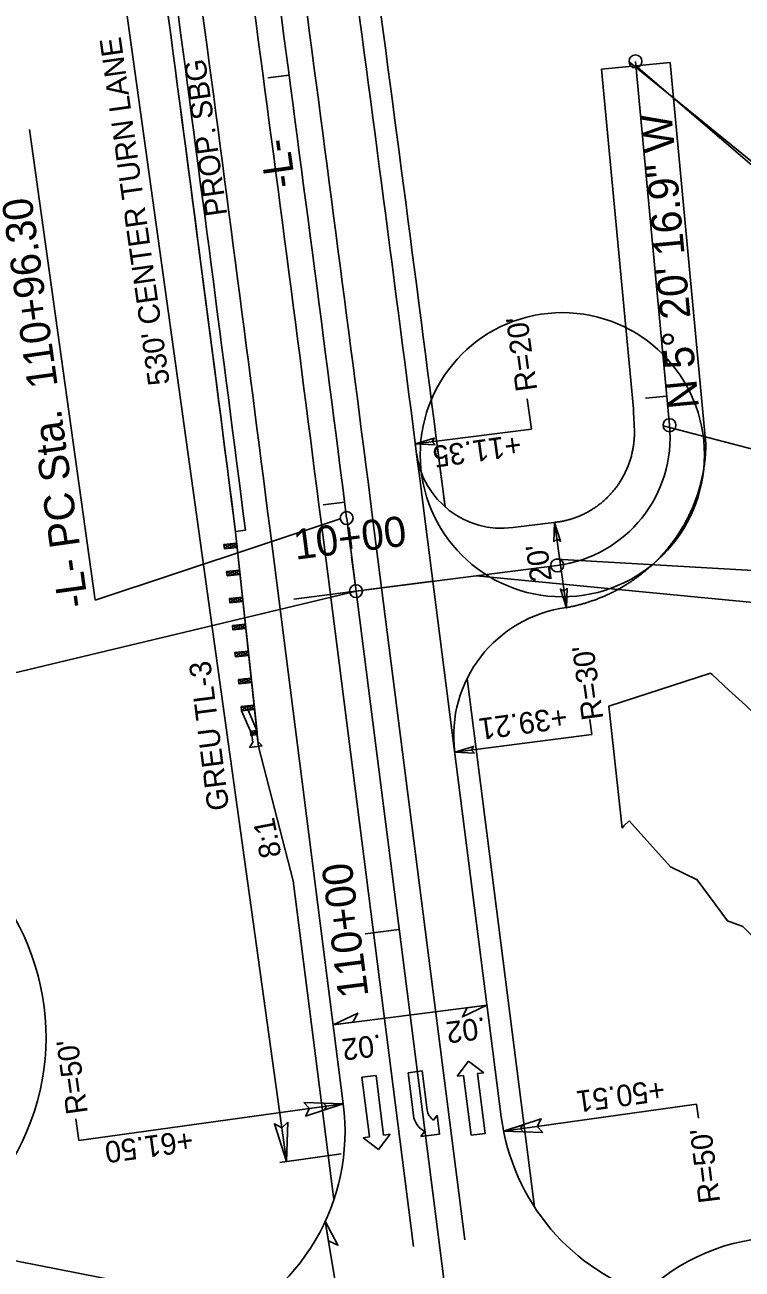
# Model space of a CAD drawing. Extents: x 472216 to 481979, y 489069 to 507339.
# Drawn here: x 477985.7 to 478152.3, y 497530.3 to 497819.2 of the extents above; entities that cross this region are included whole.
import ezdxf

# ---------------------------------------------------------------- set-up
doc = ezdxf.new("R2010")
doc.units = 0
for name, color, linetype in [('Old_Level_12', 7, 'Continuous'), ('Prop Drainage Structure Drop Inlet Grate 2 Narrow Slots and Sag Grates 840 24 CELL', 7, 'Continuous'), ('Prop Drainage Structure Drop Inlet Grate 2 Wide Slots and Sag Grates 840 22 Label', 7, 'Continuous'), ('Prop Drainage Structure Outlet Berm Ditch 850 10 CELL', 7, 'Continuous'), ('Prop Drainage Structure Pipe CSP 15in', 7, 'Continuous'), ('Prop Drainage Structure Pipe Plug CELL', 7, 'Continuous'), ('Prop Drainage Structure Pipe RCP 15in Class III Label', 7, 'Continuous'), ('Prop Drainage Structure Pipe RCP 24in Class III Label', 7, 'Continuous'), ('Prop Drainage Structure Pipe Side Drain 15in Label', 7, 'Continuous'), ('Prop Drainage Structure Tops and Inverts LABEL', 7, 'Continuous'), ('Prop Earthen Structure False Sump CELL', 7, 'Continuous'), ('Prop Earthen Structure Head Ditch', 7, 'Continuous'), ('Prop Erosion Embankment Toe Protection CELL', 7, 'Continuous'), ('Sheet Block Revision CELL', 7, 'Continuous'), ('Sheet North Arrow Point CELL', 7, 'Continuous'), ('Sheet PE Seal Cell', 7, 'Continuous'), ('Sheet Plan And Profile CELL', 7, 'Continuous'), ('Sheet Plot Border Outside CELL', 7, 'Continuous'), ('Sheet Profile Grid Major CELL', 7, 'Continuous'), ('Sheet Profile Grid Minor CELL', 7, 'Continuous')]:
    doc.layers.add(name, color=color, linetype=linetype)

msp = doc.modelspace()

# ---------------------------------------------------------------- linework, layer by layer
at = {"layer": 'Old_Level_12'}
for p, q in [((478126.01, 497810.56), (478297.2, 497671.33)), ((478127.6, 497809.67), (478261.36, 497694.97)), ((478002.05, 497685.61), (477986.84, 497794.87)), ((478133.9, 497726.09), (478246.46, 497696.58)), ((478058.97, 497704.48), (478002.05, 497685.61)), ((478109.14, 497695.17), (478233.08, 497687.85)), ((478218.13, 497678.87), (478090.63, 497691.29)), ((477920.08, 497653.64), (478062.62, 497687.71)), ((478085.17, 497512.33), (477786.24, 497570.88))]:
    msp.add_line(p, q, dxfattribs=at)
for centre in [(478127.51, 497810.7), (478135.4, 497726.23), (478060.46, 497704.67), (478060.46, 497704.67), (478109.33, 497693.68), (478062.62, 497687.71)]:
    msp.add_circle(centre, 1.5, dxfattribs=at)
at = {"layer": 'Prop Drainage Structure Drop Inlet Grate 2 Narrow Slots and Sag Grates 840 24 CELL'}
for points in [[(478093.03, 497591.58), (478087.33, 497588.85), (478088.45, 497591)], [(478057.33, 497587.03), (478063.03, 497589.76), (478061.92, 497587.61)], [(478055.48, 497541.43), (478058.43, 497535.84), (478056.24, 497536.86)]]:
    msp.add_lwpolyline(points, close=True, dxfattribs=at)
at = {"layer": 'Prop Drainage Structure Drop Inlet Grate 2 Wide Slots and Sag Grates 840 22 Label'}
for p, q in [((478057.33, 497587.03), (478093.04, 497591.58)), ((478055.48, 497541.43), (478069.85, 497454.82))]:
    msp.add_line(p, q, dxfattribs=at)
at = {"layer": 'Prop Drainage Structure Outlet Berm Ditch 850 10 CELL'}
for points in [[(478080.96, 497721.67), (478076.4, 497721.89), (478080.79, 497723.23), (478080.32, 497722.37)], [(478108.57, 497699.12), (478108.72, 497703.68), (478110.13, 497699.31), (478109.26, 497699.77)], [(478111.64, 497688.38), (478111.49, 497683.82), (478110.07, 497688.19), (478110.95, 497687.73)], [(478090.1, 497650.1), (478085.54, 497650.32), (478089.93, 497651.67), (478089.46, 497650.8)], [(478050.54, 497568.97), (478059.67, 497568.68), (478050.93, 497565.85), (478051.85, 497567.59)], [(478055.1, 497568.85), (478059.67, 497568.7), (478055.29, 497567.29), (478055.75, 497568.16)], [(478046.79, 497564.43), (478046.5, 497555.31), (478043.67, 497564.05), (478045.41, 497563.13)], [(478106.01, 497562.05), (478096.89, 497562.35), (478105.63, 497565.18), (478104.71, 497563.44)], [(478101.45, 497562.2), (478096.89, 497562.35), (478101.26, 497563.76), (478100.8, 497562.89)]]:
    msp.add_lwpolyline(points, close=True, dxfattribs=at)
at = {"layer": 'Prop Drainage Structure Pipe Plug CELL'}
for p, q in [((478034.67, 497701.38), (478039.66, 497654.89)), ((478034.94, 497698.85), (478031.95, 497698.53)), ((478033.55, 497697.69), (478031.95, 497698.53)), ((478031.95, 497698.53), (478032.06, 497697.53)), ((478032.06, 497697.53), (478033.45, 497698.69)), ((478035.04, 497697.85), (478032.06, 497697.53)), ((478033.45, 497698.69), (478033.55, 497697.69)), ((478033.45, 497698.69), (478035.04, 497697.85)), ((478033.55, 497697.69), (478034.94, 497698.85)), ((478035.04, 497697.85), (478033.55, 497697.69)), ((478034.94, 497698.85), (478035.04, 497697.85)), ((478035.61, 497692.58), (478032.57, 497692.26)), ((478034.2, 497691.42), (478032.57, 497692.26)), ((478032.57, 497692.26), (478032.68, 497691.26)), ((478032.68, 497691.26), (478034.09, 497692.42)), ((478035.72, 497691.59), (478032.68, 497691.26)), ((478034.09, 497692.42), (478034.2, 497691.42)), ((478034.09, 497692.42), (478035.72, 497691.59)), ((478035.61, 497692.58), (478034.2, 497691.42)), ((478036.28, 497686.32), (478033.25, 497685.99)), ((478034.87, 497685.16), (478033.25, 497685.99)), ((478033.25, 497685.99), (478033.36, 497685)), ((478033.36, 497685), (478034.77, 497686.15)), ((478034.77, 497686.15), (478034.87, 497685.16)), ((478034.77, 497686.15), (478036.39, 497685.32)), ((478036.28, 497686.32), (478034.87, 497685.16)), ((478036.39, 497685.32), (478033.36, 497685)), ((478036.96, 497680.05), (478033.94, 497679.73)), ((478034.04, 497678.73), (478035.45, 497679.89)), ((478035.45, 497679.89), (478035.55, 497678.89)), ((478035.45, 497679.89), (478037.06, 497679.06)), ((478036.96, 497680.05), (478035.55, 497678.89)), ((478036.96, 497680.05), (478037.06, 497679.06)), ((478035.55, 497678.89), (478033.94, 497679.73)), ((478033.94, 497679.73), (478034.04, 497678.73)), ((478037.06, 497679.06), (478034.04, 497678.73)), ((478037.63, 497673.79), (478034.51, 497673.45)), ((478036.18, 497672.63), (478034.51, 497673.45)), ((478034.51, 497673.45), (478034.62, 497672.46)), ((478034.62, 497672.46), (478036.07, 497673.62)), ((478037.73, 497672.79), (478034.62, 497672.46)), ((478036.07, 497673.62), (478036.18, 497672.63)), ((478036.07, 497673.62), (478037.73, 497672.79)), ((478037.63, 497673.79), (478036.18, 497672.63)), ((478038.3, 497667.52), (478035.32, 497667.2)), ((478036.92, 497666.37), (478035.32, 497667.2)), ((478035.32, 497667.2), (478035.43, 497666.21)), ((478035.43, 497666.21), (478036.81, 497667.36)), ((478038.41, 497666.53), (478035.43, 497666.21)), ((478036.81, 497667.36), (478036.92, 497666.37)), ((478036.81, 497667.36), (478038.41, 497666.53)), ((478038.3, 497667.52), (478036.92, 497666.37)), ((478038.97, 497661.26), (478035.93, 497660.93)), ((478037.56, 497660.1), (478035.93, 497660.93)), ((478035.93, 497660.93), (478036.03, 497659.93)), ((478036.03, 497659.93), (478037.45, 497661.09)), ((478039.08, 497660.26), (478036.03, 497659.93)), ((478036.03, 497659.93), (478038.11, 497655.23)), ((478037.45, 497661.09), (478037.56, 497660.1)), ((478037.45, 497661.09), (478039.08, 497660.26)), ((478038.97, 497661.26), (478037.56, 497660.1)), ((478037.56, 497660.1), (478039.6, 497655.39)), ((478039.6, 497655.39), (478038.11, 497655.23)), ((478038.11, 497655.23), (478038.17, 497654.73)), ((478039.71, 497654.39), (478038.11, 497655.23)), ((478038.11, 497655.23), (478038.22, 497654.23)), ((478038.22, 497654.23), (478039.6, 497655.39)), ((478039.71, 497654.39), (478038.22, 497654.23)), ((478038.37, 497654.7), (478038.98, 497654.78)), ((478038.63, 497652.67), (478038.37, 497654.7)), ((478038.98, 497654.78), (478039.59, 497654.85)), ((478039.59, 497654.85), (478039.84, 497652.82)), ((478037.93, 497651.39), (478038.63, 497652.67)), ((478040.84, 497651.76), (478037.93, 497651.39)), ((478039.84, 497652.82), (478040.84, 497651.76))]:
    msp.add_line(p, q, dxfattribs=at)
at = {"layer": 'Prop Drainage Structure Pipe RCP 15in Class III Label'}
for p, q in [((478075.99, 497535.59), (478054.5, 497703.91)), ((478087.89, 497537.11), (478066.41, 497705.43))]:
    msp.add_line(p, q, dxfattribs=at)
for radius in [22006, 21994]:
    msp.add_arc((456237.54, 494918.9), radius, 7.274664, 7.922681, dxfattribs=at)
at = {"layer": 'Prop Drainage Structure Pipe RCP 24in Class III Label'}
for p, q in [((478135.57, 497810.42), (478119.64, 497808.93)), ((478143.84, 497721.87), (478135.57, 497810.42)), ((478127.01, 497730.04), (478119.64, 497808.93)), ((478096.34, 497565.69), (478078.31, 497706.95)), ((478099.05, 497702.45), (478108.51, 497703.66)), ((478036.95, 497701.87), (478034.64, 497701.58)), ((478059.67, 497568.69), (478042.6, 497702.39))]:
    msp.add_line(p, q, dxfattribs=at)
for centre, radius, start, end in [((456237.54, 494918.9), 21982, 7.274664, 7.922681), ((456237.54, 494918.9), 22018, 7.274664, 7.90894), ((478096.51, 497722.29), 20, 187.3082, 277.2843), ((478115.3, 497654.12), 30, 97.2843, 187.2747), ((477934.66, 497584.21), 56, 329.137, 50.2504), ((478010.07, 497562.36), 50, 291.5633, 7.2747), ((478145.94, 497572.02), 50, 187.2747, 253.5242)]:
    msp.add_arc(centre, radius, start, end, dxfattribs=at)
for points in [[(478108.51, 497703.66), (478108.96, 497703.71), (478109.41, 497703.77), (478109.86, 497703.83), (478110.31, 497703.91), (478110.75, 497703.99), (478111.19, 497704.09), (478111.64, 497704.2), (478112.08, 497704.31), (478112.52, 497704.44), (478112.95, 497704.58), (478113.39, 497704.73), (478113.82, 497704.88), (478114.24, 497705.05), (478114.67, 497705.23), (478115.09, 497705.41), (478115.5, 497705.61), (478115.92, 497705.82), (478116.33, 497706.03), (478116.73, 497706.26), (478117.13, 497706.49), (478117.52, 497706.73), (478117.91, 497706.99), (478118.3, 497707.25), (478118.68, 497707.52), (478119.05, 497707.8), (478119.42, 497708.09), (478119.78, 497708.38), (478120.13, 497708.69), (478120.48, 497709), (478120.82, 497709.33), (478121.16, 497709.66), (478121.48, 497709.99), (478121.8, 497710.34), (478122.11, 497710.69), (478122.42, 497711.05), (478122.72, 497711.42), (478123, 497711.8), (478123.29, 497712.18), (478123.56, 497712.57), (478123.82, 497712.96), (478124.08, 497713.37), (478124.32, 497713.77), (478124.56, 497714.19), (478124.79, 497714.61), (478125.01, 497715.03), (478125.22, 497715.46), (478125.42, 497715.9), (478125.61, 497716.34), (478125.79, 497716.78), (478125.96, 497717.23), (478126.12, 497717.69), (478126.27, 497718.15), (478126.41, 497718.61), (478126.54, 497719.08), (478126.66, 497719.55), (478126.77, 497720.02), (478126.87, 497720.49), (478126.95, 497720.97), (478127.03, 497721.45), (478127.1, 497721.94), (478127.15, 497722.42), (478127.2, 497722.91), (478127.23, 497723.39), (478127.25, 497723.88), (478127.26, 497724.37), (478127.27, 497724.87), (478127.25, 497725.36), (478127.22, 497725.99), (478127.19, 497726.67), (478127.15, 497727.34), (478127.11, 497728.02), (478127.08, 497728.69), (478127.01, 497730.04)], [(478111.5, 497683.89), (478112.38, 497684.06), (478113.26, 497684.25), (478114.14, 497684.46), (478115, 497684.69), (478115.87, 497684.94), (478116.73, 497685.21), (478117.58, 497685.5), (478118.42, 497685.8), (478119.25, 497686.13), (478120.08, 497686.47), (478120.9, 497686.83), (478121.71, 497687.21), (478122.51, 497687.61), (478123.3, 497688.03), (478124.08, 497688.46), (478124.85, 497688.91), (478125.61, 497689.38), (478126.36, 497689.86), (478127.09, 497690.36), (478127.82, 497690.88), (478128.53, 497691.41), (478129.23, 497691.96), (478129.91, 497692.52), (478130.59, 497693.1), (478131.25, 497693.69), (478131.89, 497694.3), (478132.52, 497694.92), (478133.14, 497695.55), (478133.74, 497696.2), (478134.33, 497696.86), (478134.9, 497697.53), (478135.45, 497698.22), (478135.99, 497698.92), (478136.51, 497699.63), (478137.02, 497700.35), (478137.51, 497701.08), (478137.98, 497701.82), (478138.44, 497702.57), (478138.88, 497703.33), (478139.3, 497704.1), (478139.7, 497704.88), (478140.09, 497705.66), (478140.46, 497706.46), (478140.81, 497707.26), (478141.14, 497708.07), (478141.45, 497708.89), (478141.74, 497709.71), (478142.02, 497710.54), (478142.27, 497711.37), (478142.51, 497712.21), (478142.73, 497713.05), (478142.92, 497713.9), (478143.1, 497714.75), (478143.26, 497715.6), (478143.4, 497716.46), (478143.52, 497717.32), (478143.63, 497718.18), (478143.71, 497719.04), (478143.77, 497719.9), (478143.81, 497720.77), (478143.84, 497721.63), (478143.84, 497722.4)]]:
    msp.add_spline(points, degree=3, dxfattribs=at)
at = {"layer": 'Prop Drainage Structure Pipe Side Drain 15in Label'}
for p, q in [((478077.98, 497576.32), (478074.7, 497575.9)), ((478074.7, 497575.9), (478076.04, 497565.44)), ((478079.13, 497567.24), (478077.98, 497576.32)), ((478086.07, 497575.08), (478088.75, 497578.6)), ((478088.75, 497578.6), (478092.32, 497575.88)), ((478092.32, 497575.88), (478090.84, 497575.69)), ((478064, 497574.88), (478067.27, 497575.29)), ((478065.77, 497560.99), (478064, 497574.88)), ((478067.27, 497575.29), (478069.04, 497561.41)), ((478087.56, 497575.27), (478086.07, 497575.08)), ((478089.33, 497561.38), (478087.56, 497575.27)), ((478090.84, 497575.69), (478092.61, 497561.8)), ((478081.5, 497566.08), (478080.59, 497564.91)), ((478082.02, 497561.61), (478081.5, 497566.08)), ((478070.53, 497561.6), (478067.85, 497558.08)), ((478069.04, 497561.41), (478070.53, 497561.6)), ((478078.56, 497562.28), (478077.65, 497561.11)), ((478077.65, 497561.11), (478082.02, 497561.61)), ((478092.61, 497561.8), (478089.33, 497561.38)), ((478064.28, 497560.8), (478065.77, 497560.99)), ((478067.85, 497558.08), (478064.28, 497560.8))]:
    msp.add_line(p, q, dxfattribs=at)
for centre, radius, start, end in [((478082.37, 497567.65), 3.27, 187.2642, 236.9224), ((478081.07, 497566.88), 5.25, 195.9403, 241.252)]:
    msp.add_arc(centre, radius, start, end, dxfattribs=at)
at = {"layer": 'Prop Drainage Structure Tops and Inverts LABEL'}
msp.add_arc((456237.54, 494918.9), 21974, 7.274664, 7.922681, dxfattribs=at)
at = {"layer": 'Prop Earthen Structure False Sump CELL'}
msp.add_arc((456237.54, 494918.9), 21976.33, 7.275189, 7.922681, dxfattribs=at)
at = {"layer": 'Prop Earthen Structure Head Ditch'}
for p, q in [((478144.91, 497668.68), (478121.32, 497661.03)), ((478121.32, 497661.03), (478124.39, 497632.66))]:
    msp.add_line(p, q, dxfattribs=at)
for points in [[(478167.35, 497637.48), (478171.92, 497642.14), (478169.87, 497644.24), (478167.82, 497646.35), (478165.49, 497648.73), (478161.85, 497652.48), (478159.42, 497655.02), (478155.17, 497659.23), (478153.05, 497661.22), (478149.2, 497664.75), (478145.27, 497668.34), (478144.91, 497668.68)], [(478124.39, 497632.66), (478124.8, 497633.19), (478126.01, 497634.41)], [(478126.01, 497634.41), (478135.61, 497623.71), (478141.86, 497620.68), (478148.86, 497611.15), (478152.42, 497609.85), (478158.58, 497603.6), (478163.02, 497597.72), (478166, 497591.76), (478167, 497588.13), (478167.37, 497582.54), (478167.08, 497578.21), (478165.96, 497574.54), (478165.31, 497566.92), (478161.85, 497561.27), (478157.25, 497553.99), (478159.97, 497534.58), (478161.26, 497527.2)]]:
    msp.add_lwpolyline(points, dxfattribs=at)
at = {"layer": 'Prop Erosion Embankment Toe Protection CELL'}
for p, q in [((478083.31, 497707.26), (478081.5, 497721.49)), ((478040, 497651.66), (478034.67, 497701.38)), ((478104.06, 497544.7), (478088.4, 497667.4)), ((478040, 497651.66), (478048.02, 497620.42)), ((478057.47, 497546.44), (478048.02, 497620.42))]:
    msp.add_line(p, q, dxfattribs=at)
for radius, end in [(22023, 7.931468), (21974, 7.919388)]:
    msp.add_arc((456237.54, 494918.9), radius, 7.274664, end, dxfattribs=at)
at = {"layer": 'Sheet Block Revision CELL'}
for p, q in [((478046.5, 497555.31), (477984.51, 498000.72)), ((478103.35, 497725.33), (478102.37, 497732.37)), ((478103.35, 497725.33), (478076.4, 497721.89)), ((478111.49, 497683.82), (478108.71, 497703.69)), ((478116.89, 497657.93), (478117.38, 497654.39)), ((478117.38, 497654.39), (478085.54, 497650.32)), ((478059.67, 497568.68), (477998.3, 497560.14)), ((478096.89, 497562.35), (478141.66, 497568.58)), ((478142.11, 497565.34), (478141.66, 497568.58)), ((477998.3, 497560.14), (477997.6, 497565.18)), ((478059.2, 497557.07), (478044.91, 497555.08))]:
    msp.add_line(p, q, dxfattribs=at)
at = {"layer": 'Sheet North Arrow Point CELL'}
for p, q in [((478135.4, 497726.23), (478127.51, 497810.7)), ((478212.48, 496513.77), (478060.46, 497704.67)), ((478062.62, 497687.71), (478109.33, 497693.68))]:
    msp.add_line(p, q, dxfattribs=at)
for centre, radius, start, end in [((456237.54, 494918.9), 22000, 7.274664, 7.922681), ((478105.53, 497723.44), 30, 277.2843, 5.338)]:
    msp.add_arc(centre, radius, start, end, dxfattribs=at)
at = {"layer": 'Sheet PE Seal Cell'}
for p, q in [((478047.08, 497807.5), (478042.13, 497806.85)), ((478134.76, 497733.01), (478129.79, 497732.54)), ((478059.99, 497708.34), (478055.03, 497707.71))]:
    msp.add_line(p, q, dxfattribs=at)
at = {"layer": 'Sheet Plot Border Outside CELL'}
msp.add_line((478080.48, 497689.99), (478048.2, 497685.87), dxfattribs=at)
for centre, radius in [((478110.52, 497719.38), 32.99), ((478161.78, 497491.24), 46.45)]:
    msp.add_circle(centre, radius, dxfattribs=at)
at = {"layer": 'Sheet Profile Grid Minor CELL'}
for p, q in [((478062.62, 497687.71), (478061.61, 497695.65)), ((478072.65, 497609.14), (478064.71, 497608.13))]:
    msp.add_line(p, q, dxfattribs=at)

# ---------------------------------------------------------------- texts
at = {"layer": 'Old_Level_12'}
msp.add_text('-L- PC Sta.  110+96.30', height=7, rotation=97.9227, dxfattribs=at).set_placement((478000.5, 497684.32))
at = {"layer": 'Prop Drainage Structure Drop Inlet Grate 2 Narrow Slots and Sag Grates 840 24 CELL'}
for p in [(478092.5, 497588.81), (478068.32, 497584.83)]:
    msp.add_text('.02', height=5, rotation=187.2049, dxfattribs=at).set_placement(p)
at = {"layer": 'Prop Drainage Structure Pipe CSP 15in'}
for s, rotation, p in [("530' CENTER TURN LANE ", 98.0405, (478019.4, 497735.85)), ('PROP. SBG', 98.0406, (478032.74, 497775.11)), ("R=20'", 97.8485, (478104.73, 497734.43)), ('+11.35', 187.9227, (478100.63, 497724.15)), ("20'", 97.957, (478108.12, 497690.22)), ("R=30'", 97.8485, (478120.07, 497658.1)), ('+39.21', 187.9227, (478111.3, 497660.92)), ('8:1', 101.072, (478045.34, 497626.28)), ("R=50'", 97.9227, (478000.38, 497566.6)), ('+50.51', 187.9227, (478133.97, 497574.42)), ('+61.50', 187.9227, (478024.48, 497562.66)), ("R=50'", 96.9631, (478147.18, 497545.92))]:
    msp.add_text(s, height=5, rotation=rotation, dxfattribs=at).set_placement(p)
at = {"layer": 'Prop Drainage Structure Pipe Plug CELL'}
msp.add_text('GREU TL-3', height=5, rotation=97.2747, dxfattribs=at).set_placement((478033.19, 497637.09))
at = {"layer": 'Sheet Plan And Profile CELL'}
for s, rotation, p in [('N 5%%d 20\' 16.9" W', 95.338, (478142.24, 497730.37)), ('-L-', 97.9227, (478048.63, 497781.75))]:
    msp.add_text(s, height=7, rotation=rotation, dxfattribs=at).set_placement(p)
at = {"layer": 'Sheet Profile Grid Major CELL'}
for s, rotation, p in [('10+00', 7.2843, (478048.58, 497694.99)), ('110+00', 97.2747, (478065.54, 497593.74))]:
    msp.add_text(s, height=7, rotation=rotation, dxfattribs=at).set_placement(p)

doc.saveas('drawing.dxf')
